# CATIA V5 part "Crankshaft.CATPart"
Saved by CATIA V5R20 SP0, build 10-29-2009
Part number: Crankshaft
Material "Steel": density 7860 kg/m3, Young's modulus 2e+11 Pa, Poisson ratio 0.266, thermal expansion 1.17e-05 1/K
Bounding box of the stored display mesh (mm): x -76 to 20, y -35 to 70, z -35 to 35
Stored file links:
  E:\Ehsan\Amoozesh\CATIA\CATIA Course\Basic\Exercises\Assembly\12\Crankshaft.CATPart
  D:\CATIA V5R20\B20\intel_a\startup\materials\Catalog.CATMaterial
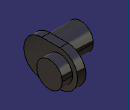
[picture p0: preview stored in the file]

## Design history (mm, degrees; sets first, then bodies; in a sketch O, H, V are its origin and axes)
Body1 (main body), material "Steel"
  Sketch1 on yz-plane, origin (0, 0, 0), H (0, 1, 0), V (0, 0, 1)
    construction line L1 (0, 0) -> (35, 0)
    line L2 (0, 35) -> (35, 35)
    line L3 (35, -35) -> (0, -35)
    arc A1 centre (35, 0) radius 35 from (35, 35) to (35, -35) cw
    arc A2 centre (0, 0) radius 35 from (0, -35) to (0, 35) cw
  Pad1: profile Sketch1, direction (-1, 0, 0), length 16
  Sketch2 on start face of Pad1, origin (0, 0, 0), H (0, 1, 0), V (0, 0, 1)
    circle A1 centre (35, 0) radius 25
  Pad2: profile Sketch2, direction (1, 0, 0), length 20
  Sketch3 on end face of Pad1, origin (-16, 0, 0), H (0, -1, 0), V (0, 0, 1)
    circle A1 centre (0, 0) radius 25
  Pad3: profile Sketch3, direction (-1, 0, 0), length 60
